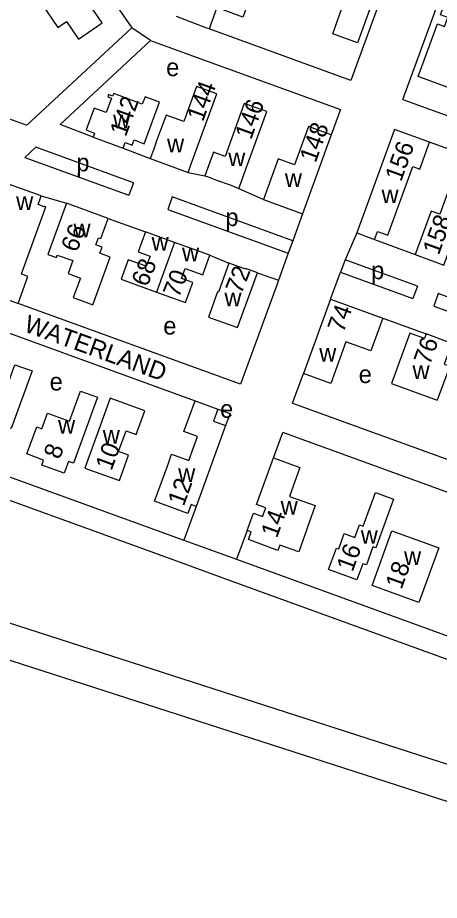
# Model space of a CAD drawing. Extents: x 154320 to 156262, y 382651 to 384180.
# Drawn here: x 155718.2 to 155813.5, y 382833.8 to 383033.1 of the extents above; entities that cross this region are included whole.
import ezdxf

# ---------------------------------------------------------------- set-up
doc = ezdxf.new("R2010")
doc.units = 0
for name, color, linetype in [('BLT_Basislijn', 7, 'Continuous'), ('BLT_Bebouwing', 7, 'Continuous'), ('BLT_Centroide', 7, 'Continuous'), ('BLT_Huisnummer', 7, 'Continuous'), ('BLT_Onderverdeling_panden', 7, 'Continuous'), ('BLT_Straatnaam', 7, 'Continuous')]:
    doc.layers.add(name, color=color, linetype=linetype)

msp = doc.modelspace()

# ---------------------------------------------------------------- linework, layer by layer
at = {"layer": 'BLT_Basislijn'}
for p, q in [((155803.59, 383046.65), (155793.51, 383018.93)), ((155805.26, 383014.66), (155815.34, 383042.38)), ((155738.6, 383038.61), (155743.96, 383030.84)), ((155720.26, 383008.83), (155743.96, 383030.84)), ((155748.2, 383027.96), (155743.96, 383030.84)), ((155727.75, 383008.97), (155748.2, 383027.96)), ((155805.26, 383014.66), (155884.39, 382985.88)), ((155711.2, 383012.17), (155720.26, 383008.83)), ((155791.12, 383012.35), (155789.05, 383006.7)), ((155735.23, 383006.14), (155727.75, 383008.97)), ((155719.79, 383001.57), (155722.26, 383003.87)), ((155744.34, 382995.84), (155722.26, 383003.87)), ((155742, 383003.67), (155748.14, 383001.31)), ((155844.57, 382992.89), (155811.27, 383005.01)), ((155719.79, 383001.57), (155743.31, 382993.02)), ((155756.7, 382998.19), (155760.49, 382997.41)), ((155768.14, 382994.54), (155773.72, 382992.05)), ((155723.5, 382992.86), (155729.25, 382991.21)), ((155780.35, 382982.75), (155753.1, 382992.66)), ((155752.09, 382989.83), (155779.33, 382979.93)), ((155782.56, 382988.85), (155780.35, 382982.75)), ((155794.84, 382984.51), (155792.22, 382978.43)), ((155780.35, 382982.75), (155779.33, 382979.93)), ((155798.86, 382983.03), (155808.04, 382979.61)), ((155761.62, 382979.49), (155765.94, 382977.66)), ((155779.33, 382979.93), (155777.11, 382973.82)), ((155792.22, 382978.43), (155791.14, 382975.63)), ((155808.53, 382972.5), (155792.22, 382978.43)), ((155772.4, 382975.52), (155777.11, 382973.82)), ((155788.85, 382969.55), (155791.14, 382975.63)), ((155791.14, 382975.63), (155807.48, 382969.69)), ((155777.11, 382973.82), (155776.8, 382972.97)), ((155776.8, 382972.97), (155768.56, 382950.32)), ((155846.86, 382958.56), (155813.21, 382970.8)), ((155768.56, 382950.32), (155718.31, 382968.6)), ((155812.2, 382967.97), (155845.84, 382955.74)), ((155780.31, 382946.05), (155782.8, 382952.74)), ((155655.02, 382946.39), (155754.06, 382910.42)), ((155780.31, 382946.05), (155835.51, 382926)), ((155766.17, 382943.74), (155765.18, 382941.02)), ((155688.54, 382939.53), (155755.76, 382915.12)), ((155776, 382933.69), (155778.11, 382939.46)), ((155847.01, 382914.39), (155778.11, 382939.46)), ((155758.53, 382922.75), (155755.76, 382915.12)), ((155770.03, 382917.33), (155767.66, 382910.8)), ((155754.06, 382910.42), (155765.95, 382906.1)), ((155765.95, 382906.1), (155852.75, 382874.58))]:
    msp.add_line(p, q, dxfattribs=at)
for points in [[(155793.51, 383018.93), (155761.49, 383030.57)], [(155748.2, 383027.96), (155758.54, 383024.19), (155791.12, 383012.35)], [(155744.34, 382995.84), (155743.31, 382993.02)], [(155753.1, 382992.66), (155752.09, 382989.83)], [(155738.66, 382987.8), (155747.04, 382984.77), (155747.04, 382984.77), (155747.04, 382984.77)], [(155808.53, 382972.5), (155807.48, 382969.69)], [(155813.21, 382970.8), (155812.2, 382967.97)], [(155699.06, 382968.15), (155758.28, 382946.61)], [(155800.7, 382965.25), (155800.7, 382965.25), (155810.47, 382961.69)], [(155763.45, 382944.73), (155766.17, 382943.74)], [(155632.33, 382923.49), (155936.55, 382825.44)], [(155755.76, 382915.12), (155767.66, 382910.8)], [(155767.66, 382910.8), (155854.46, 382879.28)], [(155657.74, 382906.9), (155933.28, 382818.09), (155939.34, 382814.58), (155944.23, 382809.86), (155948.06, 382804.8), (155950.79, 382799.64), (155952.77, 382794.44), (155952.85, 382794.13)]]:
    msp.add_lwpolyline(points, dxfattribs=at)
at = {"layer": 'BLT_Bebouwing'}
for p, q in [((155760.94, 383030.78), (155754.04, 383033.38)), ((155761.49, 383030.57), (155760.94, 383030.78)), ((155763.18, 383015.95), (155758.61, 383017.61)), ((155757.38, 383000.09), (155763.18, 383015.95)), ((155751.74, 383011.1), (155750.49, 383007.72)), ((155735.23, 383006.14), (155742, 383003.67)), ((155789.05, 383006.7), (155782.56, 382988.85)), ((155748.14, 383001.31), (155756.7, 382998.19)), ((155756.7, 382998.19), (155757.38, 383000.09)), ((155756.68, 382998.2), (155756.7, 382998.19)), ((155723.5, 382992.86), (155716.11, 382995.54)), ((155723.34, 382992.42), (155723.5, 382992.86)), ((155808.04, 382979.61), (155814.49, 382977.24)), ((155718.31, 382968.6), (155720.51, 382974.7)), ((155720.51, 382974.7), (155719.1, 382975.23)), ((155707.68, 382972.41), (155718.31, 382968.6)), ((155788.85, 382969.55), (155782.8, 382952.74)), ((155788.85, 382969.55), (155800.7, 382965.25)), ((155806.81, 382961.86), (155802.69, 382950.5)), ((155792.37, 382959.93), (155788.96, 382950.51)), ((155788.96, 382950.51), (155782.8, 382952.74)), ((155802.69, 382950.5), (155813, 382946.72)), ((155772.18, 382923.2), (155776, 382933.69)), ((155770.03, 382917.33), (155771.46, 382921.24))]:
    msp.add_line(p, q, dxfattribs=at)
for points in [[(155774.44, 383052.32), (155775.51, 383051.94), (155775.73, 383052.56), (155779.55, 383051.2), (155779.33, 383050.58), (155782.02, 383049.63), (155779.23, 383041.84), (155772.84, 383044.18), (155768.05, 383039.66), (155770.99, 383038.54), (155769.07, 383033.27), (155763.16, 383035.43), (155761.49, 383030.57)], [(155734.93, 383044.04), (155723.56, 383036.29), (155723.56, 383036.29), (155727.26, 383030.9), (155729.24, 383032.26), (155731.96, 383028.25), (155737.31, 383031.92), (155734.59, 383035.9), (155738.6, 383038.61)], [(155758.61, 383017.61), (155755.71, 383009.65), (155751.74, 383011.1)], [(155738.74, 383015.74), (155738.56, 383015.27), (155739.41, 383014.95), (155738.2, 383011.69), (155735.49, 383012.7), (155733.69, 383007.76), (155735.56, 383007.07), (155735.23, 383006.14)], [(155742, 383003.67), (155742.45, 383004.92), (155744.04, 383004.33), (155744.5, 383005.54), (155746.77, 383004.66), (155750.25, 383014.06), (155747.01, 383015.24), (155746.35, 383013.59), (155739.88, 383015.98), (155739.64, 383015.4), (155738.74, 383015.74)], [(155768.14, 382994.54), (155768.9, 382996.6), (155769.83, 382999.12), (155774.47, 383011.95), (155769.37, 383013.77), (155765.05, 383001.8), (155762.43, 383002.75), (155760.49, 382997.41)], [(155750.49, 383007.72), (155749.59, 383005.28), (155748.93, 383003.46), (155748.14, 383001.31)], [(155789.05, 383006.7), (155783.91, 383008.58), (155780.75, 382999.91), (155777.09, 383001.25), (155773.72, 382992.05)], [(155811.27, 383005.01), (155803.34, 383007.88), (155794.84, 382984.51)], [(155798.86, 382983.03), (155799.51, 382984.83), (155801.85, 382983.97), (155807.51, 382999.51), (155809.07, 382998.94), (155811.27, 383005.01)], [(155760.49, 382997.41), (155761.2, 382997.15)], [(155761.2, 382997.15), (155763.13, 382996.44), (155766.21, 382995.34), (155768.14, 382994.54)], [(155814.49, 382977.24), (155815.98, 382981.38), (155817.31, 382980.89), (155819.85, 382987.84), (155819.48, 382987.97), (155820.85, 382991.73), (155815.41, 382993.72), (155813.59, 382988.73), (155811.62, 382989.45), (155808.04, 382979.61)], [(155724.23, 382990.49), (155724.19, 382990.39), (155722.79, 382990.9), (155723.34, 382992.42)], [(155773.72, 382992.05), (155782.56, 382988.85)], [(155719.1, 382975.23), (155719.05, 382975.25), (155724.55, 382990.37), (155724.23, 382990.49)], [(155729.25, 382991.21), (155725.01, 382979.62), (155726.92, 382978.93), (155727.13, 382979.5), (155730.64, 382978.25), (155729.58, 382975.31), (155732.35, 382974.3), (155730.75, 382969.89), (155735.17, 382968.27), (155739.12, 382979.05), (155736.74, 382979.92), (155737.25, 382981.33), (155735.85, 382981.85), (155736.43, 382983.43), (155737.01, 382983.23), (155738.66, 382987.8)], [(155738.66, 382987.8), (155729.25, 382991.21)], [(155747.04, 382984.77), (155745.4, 382980.24), (155748.09, 382979.27), (155747.25, 382976.97), (155743.15, 382978.46), (155741.55, 382974.08), (155749.55, 382971.16)], [(155753.65, 382982.37), (155747.04, 382984.77)], [(155794.84, 382984.51), (155798.86, 382983.03)], [(155761.62, 382979.49), (155753.65, 382982.37)], [(155749.55, 382971.16), (155756.1, 382968.78), (155757.75, 382973.3), (155755.22, 382974.22), (155756.05, 382976.49), (155760.02, 382975.06), (155761.62, 382979.49)], [(155765.94, 382977.66), (155763.56, 382971.12), (155763.36, 382971.19), (155761.28, 382965.51), (155767.88, 382963.12), (155772.4, 382975.52)], [(155772.4, 382975.52), (155769.78, 382976.47), (155769.71, 382976.29), (155765.94, 382977.66)], [(155800.7, 382965.25), (155798.01, 382957.88), (155792.37, 382959.93)], [(155810.47, 382961.69), (155810.1, 382960.66), (155806.81, 382961.86)], [(155816.27, 382959.55), (155810.47, 382961.69)], [(155816.27, 382959.55), (155814.55, 382954.88), (155815.83, 382954.41), (155813, 382946.72)], [(155758.53, 382922.75), (155757.36, 382923.17), (155756.63, 382921.17), (155749.1, 382923.9), (155752.08, 382932.09), (155752.96, 382934.53), (155756.87, 382933.11), (155758.83, 382938.54), (155755.75, 382939.66), (155758.28, 382946.61)], [(155758.28, 382946.61), (155763.45, 382944.73)], [(155763.45, 382944.73), (155762.46, 382942.01), (155765.18, 382941.02)], [(155765.18, 382941.02), (155759.42, 382925.22)], [(155776, 382933.69), (155781.97, 382931.56), (155779.64, 382925.01), (155785.43, 382922.96), (155781.7, 382912.46), (155777.4, 382913.99), (155776.97, 382912.82), (155770.34, 382915.24), (155770.97, 382916.99), (155770.03, 382917.33)], [(155759.42, 382925.22), (155758.53, 382922.75)], [(155771.46, 382921.24), (155773.54, 382920.48), (155774.25, 382922.45), (155772.18, 382923.2)]]:
    msp.add_lwpolyline(points, dxfattribs=at)
for points in [[(155790.29, 383047.26), (155800.81, 383043.44), (155794.99, 383027.46), (155789.43, 383029.47), (155791.92, 383036.56), (155790.58, 383037.04), (155792.62, 383042.69), (155789.09, 383043.98)], [(155815.34, 383038.14), (155826.66, 383034.03), (155823.68, 383025.81), (155821.96, 383021.11), (155817.81, 383022.67), (155817.2, 383020.97), (155818.61, 383020.47), (155817.26, 383016.69), (155808.67, 383019.81), (155813.04, 383031.76), (155814.64, 383031.16), (155815.37, 383033.18), (155813.77, 383033.75)], [(155717.53, 382954.75), (155721.43, 382953.34), (155716.72, 382940.34), (155715.79, 382940.68), (155713.92, 382935.55), (155706.97, 382938.09), (155711.57, 382950.61), (155715.47, 382949.11)], [(155732.39, 382948.78), (155736.22, 382947.39), (155730.79, 382932.48), (155729.64, 382932.9), (155728.67, 382930.24), (155723.63, 382932.07), (155724.05, 382933.22), (155720.28, 382934.59), (155722.5, 382940.7), (155723.64, 382940.28), (155724.94, 382943.82), (155729.92, 382942.02)], [(155739.1, 382947.21), (155733.36, 382931.41), (155741.16, 382928.58), (155743.26, 382934.34), (155741, 382935.16), (155742.7, 382939.84), (155744.96, 382939.02), (155746.9, 382944.37)], [(155799.03, 382925.92), (155803.14, 382924.42), (155799.12, 382913.37), (155798.47, 382913.61), (155796.98, 382909.53), (155796.18, 382909.8), (155794.85, 382906.15), (155788.46, 382908.49), (155790.22, 382913.33), (155790.74, 382913.15), (155792, 382916.63), (155794.39, 382915.76), (155795.43, 382918.59), (155796.25, 382918.3)], [(155798.33, 382904.86), (155802.78, 382917.23), (155813.34, 382913.43), (155808.88, 382901.06)]]:
    msp.add_lwpolyline(points, close=True, dxfattribs=at)
at = {"layer": 'BLT_Onderverdeling_panden'}
msp.add_line((155753.65, 382982.37), (155749.55, 382971.16), dxfattribs=at)

# ---------------------------------------------------------------- texts
at = {"layer": 'BLT_Centroide'}
for s, p in [('e', (155751.72, 383019.94)), ('p', (155731.42, 382998.43)), ('p', (155765.11, 382986.07)), ('p', (155798.05, 382974.06)), ('e', (155751.07, 382961.57)), ('e', (155795.24, 382950.62)), ('e', (155725.39, 382948.95)), ('e', (155763.92, 382942.78))]:
    msp.add_text(s, height=4, rotation=359.5, dxfattribs=at).set_placement(p)
for p in [(155739.75, 383008.12), (155751.94, 383002.7), (155765.77, 382999.6), (155778.57, 382994.9), (155800.41, 382991.24), (155717.83, 382989.67), (155730.8, 382983.54), (155748.44, 382980.51), (155755.33, 382978.11), (155764.91, 382967.95), (155786.33, 382955.44), (155807.42, 382951.5), (155727.31, 382939.18), (155737.41, 382936.94), (155754.45, 382928.26), (155777.62, 382920.89), (155795.72, 382914.31), (155805.5, 382909.52)]:
    msp.add_text('w', height=4, dxfattribs=at).set_placement(p)
at = {"layer": 'BLT_Huisnummer'}
for s, rotation, p in [('144', 70.0179, (155760.04, 383009.46)), ('142', 70.0179, (155742.62, 383006.07)), ('146', 70.0179, (155770.93, 383005.39)), ('148', 70.0179, (155785.51, 383000.16)), ('156', 70.0179, (155804.83, 382995.9)), ('158', 70.0179, (155813.34, 382979.31)), ('66', 68.284, (155731.53, 382979.94)), ('68', 68.284, (155747.46, 382972.15)), ('70', 68.284, (155754.58, 382969.65)), ('72', 68.284, (155768.71, 382970.5)), ('74', 70.0179, (155791.81, 382961.79)), ('76', 70.0179, (155811.31, 382954.47)), ('8', 70.0181, (155727.68, 382933.19)), ('10', 70.0174, (155739.38, 382930.64)), ('12', 70.0174, (155755.71, 382922.61)), ('14', 70.0174, (155776.77, 382915.43)), ('16', 70.0174, (155793.87, 382907.8)), ('18', 70.0191, (155804.92, 382903.83))]:
    msp.add_text(s, height=4, rotation=rotation, dxfattribs=at).set_placement(p)
at = {"layer": 'BLT_Straatnaam'}
msp.add_text('WATERLAND', height=4, rotation=340.1818, dxfattribs=at).set_placement((155719.35, 382962.35))

doc.saveas('drawing.dxf')
